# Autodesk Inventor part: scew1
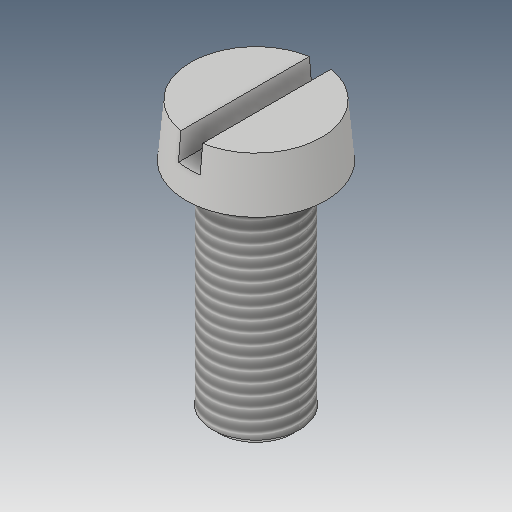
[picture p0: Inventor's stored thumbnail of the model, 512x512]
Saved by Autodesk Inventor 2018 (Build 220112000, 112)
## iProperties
Created: 2016-05
Part Number: scew1
Material: Generic
Document SubType Name: Modeling
Designer: CADCIM
Density: 1 g/cm^3
Appearance: Default
Author: CADCIM
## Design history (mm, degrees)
sketch "Sketch1"
  geometry: C1 r 9.6 at (0, 0); 1 further point
  constraints: 1 centre point, 1 coincident
  dimensions: "d0" = 19.2 diameter of C1
extrude "Extrusion1" new body sketch "Sketch1" distance "d1" = 7.2; taper "d2" = -5 deg
sketch "Sketch3"
  geometry: C1 r 6 at (0, 0); 1 further point
  constraints: 1 centre point, 1 coincident
  dimensions: "d7" = 12 diameter of C1
extrude "Extrusion3" join sketch "Sketch3" distance "d8" = 30; taper "d9" = 0 deg
thread "Thread1" dims "d13" = 10, "d14" = 0
chamfer "Chamfer2" distance "d15" = 0.9; stored, may be unused: second distance "d16" = 2, angle "d17" = 45 deg
sketch "Sketch4"
  geometry: L1 (1.5, -10.35)-(-1.5, -10.35); L2 (-1.5, -10.35)-(-1.5, 10.35); L3 (-1.5, 10.35)-(1.5, 10.35); L4 (1.5, 10.35)-(1.5, -10.35); L5 (0, -10.35)-(0, 10.35); 2 further points
  constraints: 10 end point, 3 midpoint, 2 parallel, 1 coincident, 1 horizontal, 1 perpendicular
  dimensions: "d18" = 3 distance of L1.start L1.end
extrude "Extrusion4" cut sketch "Sketch4" distance "d19" = 3.6; taper "d20" = 0 deg
body "Solid1"
